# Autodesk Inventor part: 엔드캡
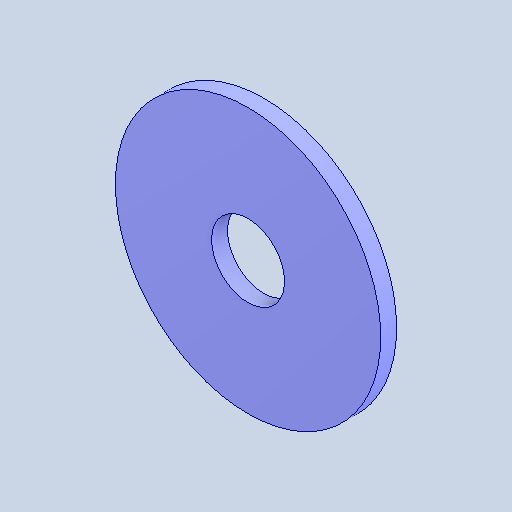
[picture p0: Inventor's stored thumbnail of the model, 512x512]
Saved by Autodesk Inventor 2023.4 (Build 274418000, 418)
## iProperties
Created: 2024-09
Part Number: 엔드캡
Material: 강철, 연강
Document SubType Name: Modeling
Designer: 11
Density: 7.85 g/cm^3
Appearance: 기본값
Author: jhkim
Sending System: Autodesk Inventor 2025
Preprocessor: ST-DEVELOPER v20
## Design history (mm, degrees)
node "엔드캡1"
node "솔리드2"
node "솔리드1"
